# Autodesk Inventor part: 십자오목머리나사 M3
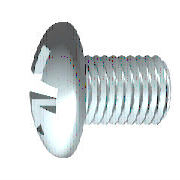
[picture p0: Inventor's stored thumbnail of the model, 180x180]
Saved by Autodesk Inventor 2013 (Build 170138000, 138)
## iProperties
Created: 2012-02
Part Number: 십자오목머리나사 M3
Material: 강철, 연강
Description: 십자 오목 머리 나사
Document SubType Name: Modeling
Standard: KS B 1023
Designer: mduedu
Standards Organization: KS
Language: ko-KR
Size Designation: A  M 3 x 6 - H
Categories: <MemberInstance><Categories><Category DisplayName="조임쇠" InternalName="e4da775c-781d-43d5-af7c-5136215cf5a6" Mnemonic="FSTN"><Category DisplayName="볼트" InternalN
Density: 7.86 g/cm^3
Mass: 0.662366 g
Surface Area: 1.40192 cm^2
Volume: 0.0842705 cm^3
IsCustomPart: 0
Author: mduedu
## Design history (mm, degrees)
body "Solid1"
workplane "Work Plane3"
sketch "스케치2"
  geometry: L1 (-3.72, 0)-(3.72, 0) reference; L2 (0, -3.72)-(0, 3.72) reference; L3 (0, 1.5)-(0, 0); L4 (0, 0)-(1.5, 0); L5 (0, 0)-(1.879, 1.879); L6 (0.253, 1.479)-(0.261, 0.456); L7 (1.479, 0.253)-(0.456, 0.261); L8 (0.253, -1.479)-(0.261, -0.456); L9 (1.479, -0.253)-(0.456, -0.261); L10 (-0.253, 1.479)-(-0.261, 0.456); L11 (-1.479, 0.253)-(-0.456, 0.261); L12 (-1.479, -0.253)-(-0.456, -0.261); L13 (-0.253, -1.479)-(-0.261, -0.456); A1 r 0.45 centre (0, 0) between (0.45, 0) and (0, 0.45); A2 r 1.5 centre (0, 0) between (1.5, 0) and (1.479, 0.253); A3 r 1.5 centre (0, 0) between (0.253, 1.479) and (0, 1.5); A4 r 1.5 centre (0, 0) between (1.479, 0.253) and (0.253, 1.479); A5 r 1.5 centre (0, 0) between (0, -1.5) and (0.253, -1.479); A6 r 1.5 centre (0, 0) between (0.253, -1.479) and (1.479, -0.253); A7 r 1.5 centre (0, 0) between (1.479, -0.253) and (1.5, 0); A8 r 1.5 centre (0, 0) between (-1.479, 0.253) and (-1.5, 0); A9 r 1.5 centre (0, 0) between (-0.253, 1.479) and (-1.479, 0.253); A10 r 1.5 centre (0, 0) between (0, 1.5) and (-0.253, 1.479); A11 r 1.5 centre (0, 0) between (-1.5, 0) and (-1.479, -0.253); A12 r 1.5 centre (0, 0) between (-1.479, -0.253) and (-0.253, -1.479); A13 r 1.5 centre (0, 0) between (-0.253, -1.479) and (0, -1.5); A14 r 0.525 centre (0, 0) between (0.525, 0) and (0, 0.525); A15 r 0.197 centre (0.457, 0.457) between (0.261, 0.456) and (0.456, 0.261); A16 r 0.197 centre (0.457, -0.457) between (0.456, -0.261) and (0.261, -0.456); A17 r 0.197 centre (-0.457, 0.457) between (-0.456, 0.261) and (-0.261, 0.456); A18 r 0.197 centre (-0.457, -0.457) between (-0.261, -0.456) and (-0.456, -0.261); 1 further point
  constraints: 38 point on circle, 22 end point, 19 symmetric about line, 18 centre point, 4 coincident, 3 collinear, 3 point on line, 3 tangent, 1 perpendicular, 21 other
  dimensions: "d4" = 45 deg angle of L5 L4; "d5" = 0.9 diameter of A1 (= 0.3 x SDM); "d6" = 3 diameter of A4 (= SDM); "d7" = 0.2525 distance from line of L6.start L3 (= 0.5 x SBR); "d14" = 1.05 diameter of A14 (= 0.35 x SDM)
extrude "슬롯" join sketch "스케치2" taper "d15" = 5 deg; stored distance "d54" = 10
revolve "절단부" stored, may be unused: angle "d56" = 90 deg
revolve "본체" stored, may be unused: angle "d18" = 90 deg
workplane "Work Plane1"
sketch "스케치1"
  geometry: L1 (6, 0)-(6, 1.5); L2 (6, 1.5)-(1, 1.5); L3 (3.962, 5.08)-(3.962, 5.08); L4 (-2.4, 0)-(-2.4, 2.59); L5 (-2.2, 1.4)-(-1.036, 0.82); L6 (-1.036, 0.82)-(-0.6, 0); L7 (-0.6, 0)-(6, 0); L8 (-4.305, 0)-(7.717, 0) reference; L9 (0, -1.016)-(0, 6.096) reference; L10 (-2.2, 1.4)-(-2.4, 1.5); L11 (-1.636, 2.657)-(-2.4, 2.59); L12 (-1.636, 2.657)-(0, 2.8); L13 (0, 2.8)-(0, 1.347); L14 (0, 1.347)-(0.693, 1.347); L15 (0.693, 1.347)-(1, 1.5); L16 (1, 1.5)-(0, 1.5); A1 r 5 centre (2.6, 0) between (-1.636, 2.657) and (-2.4, 0)
  constraints: 28 end point, 5 point on line, 4 collinear, 4 point on circle, 3 parallel, 2 perpendicular, 1 centre point, 1 horizontal, 1 tangent
  dimensions: "d1" = 3 diameter of L2 L7 (= GD); "d2" = 1.8 distance from line of L6.end L4 (= STI); "d11" = 3 diameter of L10.end L7 (= SDM); "d12" = 62 deg angle of L6 L7; "d13" = 26.5 deg angle of L5 L7; "d17" = 5.6 diameter of L12.end L7 (= KOD); "d19" = 5 deg angle of L12 L7 (= KEWI); "d20" = 2.4 distance between parallel lines of L4 L13 (= KOH); "d21" = 5 radius of A1 (= KR); "d23" = 2.6935 diameter of L14 L7 (= BDM); "d24" = 5 distance of L1.end L2.end (= GEL); "d25" = 0.30673 horizontal distance of L14.end L2.end (= GAL); "d28" = 6 distance between parallel lines of L1 L13 (= NLG)
fillet "모깎기1" dims "d29" = 1.2 (= RR)
fillet "모깎기2" dims "d16" = 0.101 (= 0.2 x SBR)
feature "스레드" dims "d8" = 5 (= GEL), "d9" = 0
chamfer "모따기1" distance "d26" = 0.30673 (= -0.5 x SPD + 0.5 x GD); stored, may be unused: second distance "d27" = 0.30683 (computed from GUL), angle "d78" = 45 deg
other parameters: "GD" = 3 (= NND) [user parameter; used in 2 equation terms], "NLG" = 6 [user parameter; used in 1 equation term], "GEL" = 5 [user parameter; used in 2 equation terms], "KOD" = 5.6 [user parameter; used in 1 equation term], "KOH" = 2.4 [user parameter; used in 2 equation terms], "SDM" = 3 [user parameter; used in 4 equation terms], "STI" = 1.8 [user parameter; used in 1 equation term], "SBR" = 0.505 [user parameter; used in 2 equation terms], "GAL" = 0.30673 (= 0.61345 x PTC) [user parameter; used in 1 equation term], "SPD" = 2.38655 (= NND - 1.2269 x PTC) [user parameter; used in 1 equation term], "KEWI" = 5 deg [user parameter; used in 1 equation term], "d3" = -2.4 (= -KOH), "d10" = 0, "KR" = 5 [user parameter; used in 1 equation term], "BDM" = 2.6935 [user parameter; used in 1 equation term], "GUL" = 0.30673 (= 0.61345 x PTC) [user parameter; used in 1 equation term], "RR" = 1.2 [user parameter; used in 1 equation term], "d79" = 0, "d80" = 0, "PTC" = 0.5 [user parameter; used in 5 equation terms], "THREADDIA" = 3 [user parameter; used in 1 equation term], "TOA" = 30 deg [user parameter], "NND" = 3 [user parameter; used in 2 equation terms], "GD1" = 2.38655 (= THREADDIA - 1.2269 x PTC) [user parameter]
